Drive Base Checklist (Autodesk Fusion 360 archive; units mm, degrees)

design "Drive Base Checklist" references "AM14U Family End Plate", "19 Tooth, 3/8  Hex Gear", "1/4-20 x 0.75  Thread Rolling Screw", "Bearing FR8ZZ Hex", "TB Mini S Small Hex Shaft", "10-32 Nylock Nut", "10-32 x 0.5  SHCS", "500 churro", "AM14U6 Outer Plate", "CIM gear 14 tooth", "Bearing FR8ZZ", "Spacer 0.850in x 0.380in", "1/2  E-Clip Ring", "45 Tooth, 1/2  Hex Gear", "8mm Push on Retaining Ring", "50 Tooth, 3/8  Hex Gear", "3/8-16 x 4.25  HHS Bolt", "500 Churro, 3.375", "1/2  Hex Hub", "6in HiGrip Wheel", "AM14U6 Inner Plate", "ToughBox Mini Housing", "Half Pulley 42t", "1/2  Hex Output Shaft Encoder Pin Ready", "1614ZZ Bearing", "10-32 x 0.75  SHCS", "Bearing FR6ZZ", "Bearing R6ZZ", "Spacer 0.280in x 0.382in"
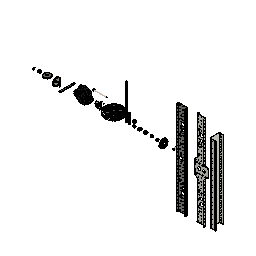
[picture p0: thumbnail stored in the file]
component_insert "Component Insert1"
component_insert "Component Insert2"
component_insert "Component Insert6"
component_insert "Component Insert7"
component_insert "Component Insert8"
component_insert "Component Insert9"
component_insert "Component Insert11"
component_insert "Component Insert14"
component_insert "Component Insert17"
component_insert "Component Insert18"
component_insert "Component Insert21"
component_insert "Component Insert22"
component_insert "Component Insert23"
component_insert "Component Insert24"
component_insert "Component Insert25"
component_insert "Component Insert26"
component_insert "Component Insert27"
component_insert "Component Insert28"
component_insert "Component Insert29"
component_insert "Component Insert30"
component_insert "Component Insert31"
component_insert "Component Insert32"
component_insert "Component Insert33"
component_insert "Component Insert34"
component_insert "Component Insert35"
component_insert "Component Insert36"
component_insert "Component Insert37"
component_insert "Component Insert38"
component_insert "Component Insert39"

design "Bearing FR8ZZ"
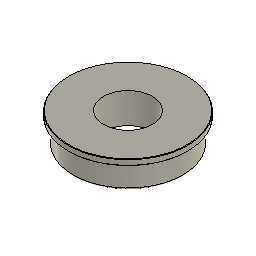
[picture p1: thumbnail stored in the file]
base_feature "Base Feature"

design "3/8-16 x 4.25  HHS Bolt"
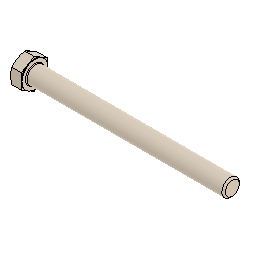
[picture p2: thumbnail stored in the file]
description: 375-16 x 4.25 Hex Bolt_HFBOLT 0.375-16x2.5x1-C
part number: 375-16 x 4.25 Hex Bolt_HFBOLT 0.375-16x2.5x1-C
base_feature "Base Feature"

design "45 Tooth, 1/2  Hex Gear"
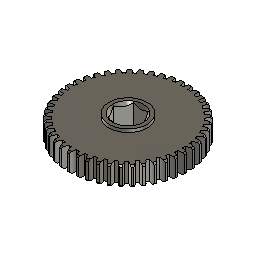
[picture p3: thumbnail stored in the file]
description: STEP AP203
part number: am-4712 45T 20DP 500hex Standard Gear
base_feature "Base Feature"

design "Bearing FR6ZZ"
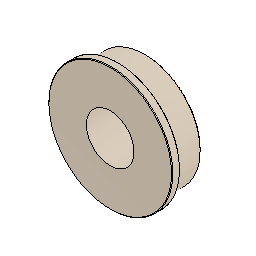
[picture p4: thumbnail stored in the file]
base_feature "Base Feature"

design "1/4-20 x 0.75  Thread Rolling Screw"
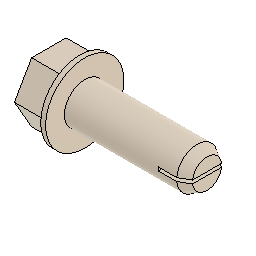
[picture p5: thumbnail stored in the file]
description: FHTS 0.25-20-0.75_Square Configuration
part number: FHTS 0.25-20-0.75_Square Configuration
base_feature "Base Feature"

design "ToughBox Mini Housing"
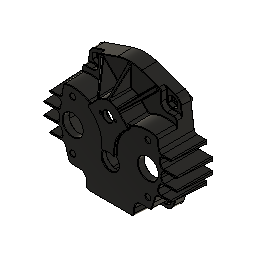
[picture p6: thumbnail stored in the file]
description: ToughBox Mini Housing
part number: ToughBox Mini Housing
base_feature "Base Feature"

design "50 Tooth, 3/8  Hex Gear"
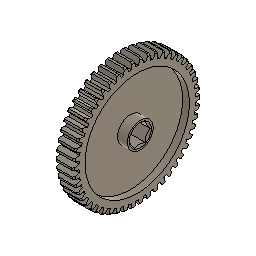
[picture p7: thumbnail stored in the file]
description: 50T 20DP 375hex 375 FW
part number: 50T 20DP 375hex 375 FW
base_feature "Base Feature"

design "1/2  E-Clip Ring"
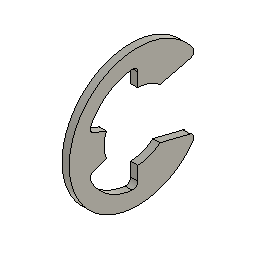
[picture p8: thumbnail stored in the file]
description: am-0206 1-2 in Shaft External Klipring_97431A340
part number: am-0206 1-2 in Shaft External Klipring_97431A340
base_feature "Base Feature"

design "10-32 Nylock Nut"
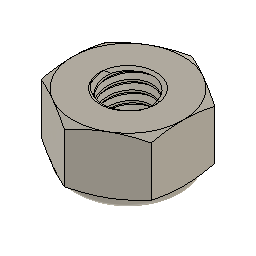
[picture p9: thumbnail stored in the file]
description: am-1042 10-32 Nylock Nut_90631A411
part number: am-1042 10-32 Nylock Nut_90631A411
base_feature "Base Feature"

design "AM14U6 Outer Plate"
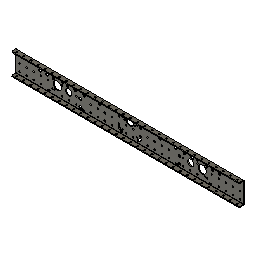
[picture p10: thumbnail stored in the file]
description: STEP AP203
part number: am-3921b AM14U5 On Grid Outside Plate
base_feature "Base Feature"

design "6in HiGrip Wheel"
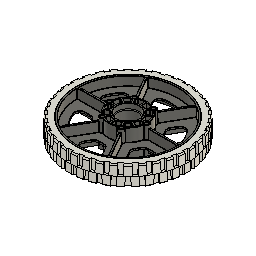
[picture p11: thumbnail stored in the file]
base_feature "Base Feature1"
base_feature "Base Feature1"
as_built_joint "As-built1"
joint "Assemble1" alignAngle 180 alignOffsetX 0 alignOffsetY 0 alignOffsetZ 0
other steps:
create_component "CreateComponent1"
create_component "CreateComponent2"
joint_origin "JointOrigin1"
joint_origin "JointOrigin1"

design "19 Tooth, 3/8  Hex Gear"
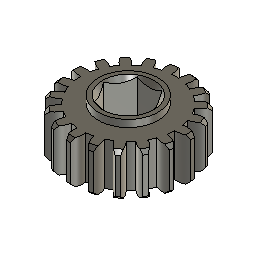
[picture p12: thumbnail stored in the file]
description: STEP AP203
part number: am-3645 19T 20DP 375hex Standard Gear
base_feature "Base Feature"

design "1614ZZ Bearing"
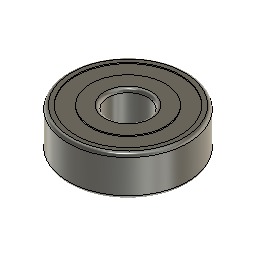
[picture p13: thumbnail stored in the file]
description: STEP AP203
part number: am-0209 375in ID 1125in OD Shielded Bearing 1614ZZ
base_feature "Base Feature"

design "8mm Push on Retaining Ring"
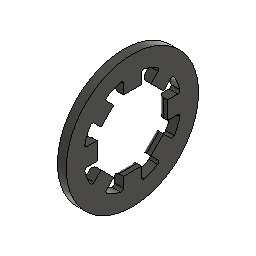
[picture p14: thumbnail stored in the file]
description: CIM Shaft Clip
part number: CIM Shaft Clip
base_feature "Base Feature"

design "Half Pulley 42t"
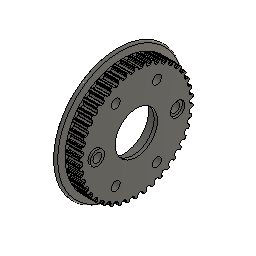
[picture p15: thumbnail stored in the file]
base_feature "Base Feature"

design "Bearing R6ZZ"
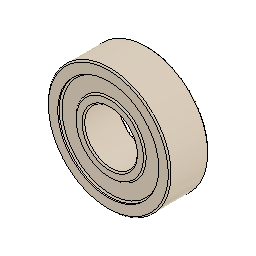
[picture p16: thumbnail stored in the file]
base_feature "Base Feature"

design "AM14U Family End Plate"
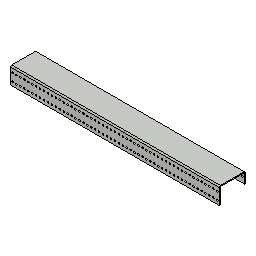
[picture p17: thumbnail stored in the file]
description: am-3920 AM14U Family End Plate_Square Configuration
part number: am-3920 AM14U Family End Plate_Square Configuration
base_feature "Base Feature"

design "AM14U6 Inner Plate"
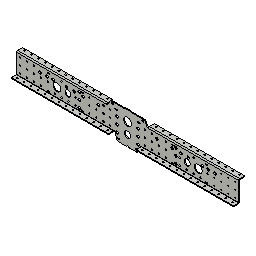
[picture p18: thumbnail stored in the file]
description: STEP AP214
part number: am-3922b AM14U6 Inside Plate
base_feature "Base Feature"

design "1/2  Hex Hub"
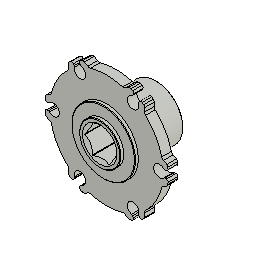
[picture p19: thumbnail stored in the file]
description: STEP AP214
part number: am-2568 500EX Hex Hub
base_feature "Base Feature"

design "CIM gear 14 tooth"
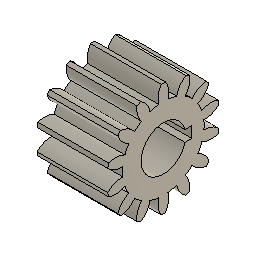
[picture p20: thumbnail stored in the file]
base_feature "Base Feature"

design "500 Churro, 3.375"
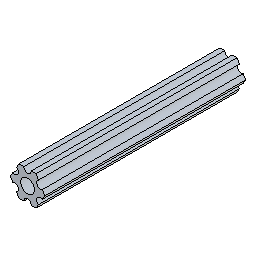
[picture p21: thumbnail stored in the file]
description: 3.375in Churro_Square Configuration
part number: 3.375in Churro_Square Configuration
base_feature "Base Feature"

design "1/2  Hex Output Shaft Encoder Pin Ready"
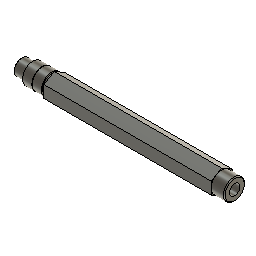
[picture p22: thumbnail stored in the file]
description: STEP AP203
part number: am-4722 ToughBox S AM14U5 Hex Output Shaft
base_feature "Base Feature"

design "10-32 x 0.75  SHCS"
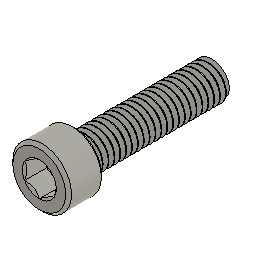
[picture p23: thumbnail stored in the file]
description: am-1047 10-32 x 0750 SHCS_90128A945
part number: am-1047 10-32 x 0750 SHCS_90128A945
base_feature "Base Feature"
